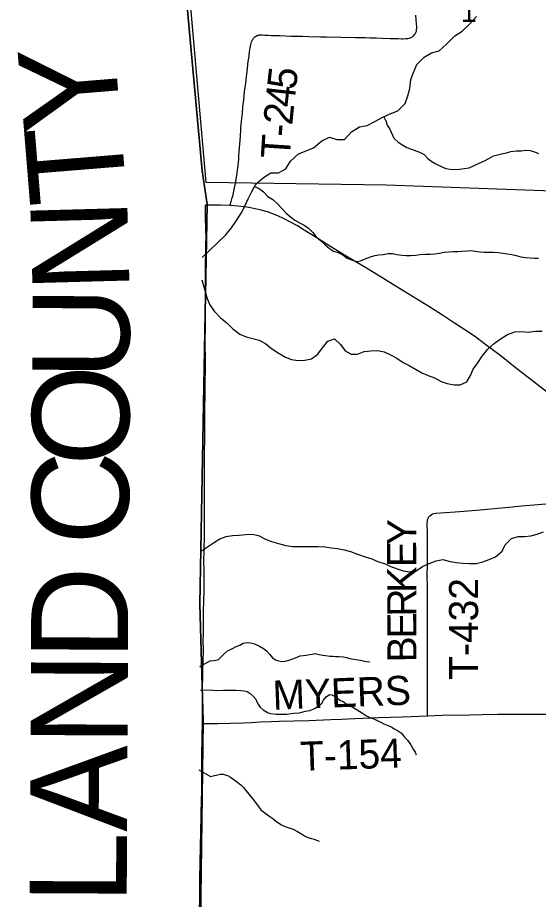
# Model space of a CAD drawing. Extents: x 1985906 to 2360102, y 891258 to 1222054.
# Drawn here: x 2070264 to 2075633, y 1044417 to 1053500 of the extents above; entities that cross this region are included whole.
import ezdxf

# ---------------------------------------------------------------- set-up
doc = ezdxf.new("R2010")
doc.units = 0
for name, color, linetype in [('GM_X_Adjacent_County', 7, 'Continuous'), ('GM_X_Adjacent_County_Text', 7, 'Continuous'), ('GM_X_County', 7, 'Continuous'), ('GM_X_Minor_River', 7, 'Continuous'), ('GM_X_Section', 7, 'Continuous'), ('GM_X_Section_Text', 7, 'Continuous'), ('GM_X_State_Route', 7, 'Continuous'), ('GM_X_Township', 7, 'Continuous'), ('GM_X_Township_Road', 7, 'Continuous'), ('GM_X_Township_Road_Text', 7, 'Continuous')]:
    doc.layers.add(name, color=color, linetype=linetype)

msp = doc.modelspace()

# ---------------------------------------------------------------- linework, layer by layer
at = {"layer": 'GM_X_Adjacent_County'}
msp.add_lwpolyline([(2071926.7, 1054555.3), (2072166.7, 1051922.6), (2072218.3, 1051577.8), (2072142.8, 1047459), (2072178.7, 1046252), (2072112.2, 1041354.4), (2072120.2, 1038512.6), (2072055.1, 1036106.6), (2072018.3, 1033424.1), (2071939.9, 1030867.8), (2071602.1, 1025081.7), (2071562, 1025081.6), (2071696.9, 1021700.4), (2071829.8, 1014456.9), (2071852.3, 1012905.1), (2071861.2, 1011952), (2071887.5, 1008769)], dxfattribs=at)
at = {"layer": 'GM_X_County'}
msp.add_lwpolyline([(2071887.5, 1008769), (2071861.2, 1011952), (2071852.3, 1012905.1), (2071829.8, 1014456.9), (2071696.9, 1021700.4), (2071562, 1025081.6), (2071602.1, 1025081.7), (2071939.9, 1030867.8), (2072018.3, 1033424.1), (2072055.1, 1036106.6), (2072120.2, 1038512.6), (2072112.2, 1041354.4), (2072178.7, 1046252), (2072142.8, 1047459), (2072218.3, 1051577.8), (2072166.7, 1051922.6), (2071926.7, 1054555.3)], dxfattribs=at)
at = {"layer": 'GM_X_Minor_River'}
for points in [[(2072166, 1051027.7), (2072324, 1051178.6), (2072407.5, 1051259.9), (2072468.8, 1051335.4), (2072522.1, 1051411), (2072569.4, 1051484.6), (2072606.6, 1051558.4), (2072641.8, 1051634.3), (2072677, 1051708.1), (2072720.3, 1051783.8), (2072799.6, 1051853.1), (2072874.6, 1051902.3), (2072952.9, 1051901.2), (2073029.8, 1051942.4), (2073077.1, 1052020.1), (2073158.5, 1052095.3), (2073239.3, 1052126.3), (2073316.1, 1052159.5), (2073399.4, 1052230.6), (2073478.3, 1052269.8), (2073554.3, 1052244.6), (2073634.6, 1052245.6), (2073706, 1052322.9), (2073787.1, 1052374.1), (2073867.6, 1052389.1), (2073946.5, 1052430.2), (2074021.4, 1052471.3), (2074106.3, 1052510.4), (2074183.1, 1052541.5), (2074260.5, 1052616.8), (2074285.7, 1052692.7), (2074306.9, 1052770.8), (2074318.2, 1052861), (2074345.4, 1052934.9), (2074380.7, 1053018.8), (2074454.1, 1053094.1), (2074531, 1053137.3), (2074609.6, 1053158.3), (2074684.9, 1053227.6), (2074770.5, 1053312.8), (2074847.5, 1053360), (2074922.8, 1053431.3), (2074994.3, 1053510.6)], [(2074039.3, 1052479.6), (2074059.1, 1052436.7), (2074074.5, 1052392.3), (2074100, 1052349.8), (2074142.9, 1052256.9), (2074186.5, 1052218.1), (2074234.2, 1052185.3), (2074278.1, 1052160.7), (2074324, 1052144), (2074407.9, 1052114.8), (2074455.8, 1052090), (2074493.3, 1052047.3), (2074535.1, 1052016.6), (2074576.9, 1051994), (2074630.7, 1051965.2), (2074678.6, 1051946.5), (2074724.7, 1051939.8), (2074772.9, 1051937.2), (2074819.1, 1051940.6), (2074867.4, 1051945.9), (2074917.7, 1051953.3), (2075022.8, 1052000.1), (2075077.4, 1052025.5), (2075121.9, 1052049), (2075168.5, 1052076.5), (2075210.9, 1052087.9), (2075253.1, 1052095.4), (2075303.5, 1052106.8), (2075347.9, 1052120.3), (2075406.2, 1052127.5), (2075454.4, 1052128.9), (2075500.7, 1052134.3), (2075546.9, 1052131.7), (2075592.9, 1052119), (2075634.8, 1052100.4)], [(2072706.7, 1051760.1), (2072753.8, 1051739.2), (2072797.5, 1051704.5), (2072845, 1051657.7), (2072896.7, 1051624.8), (2072944.3, 1051582.1), (2072991.8, 1051531.2), (2073033.3, 1051484.5), (2073076.9, 1051447.7), (2073120.6, 1051415), (2073176.4, 1051384.1), (2073218.3, 1051363.5), (2073264.1, 1051332.8), (2073307.6, 1051288), (2073343.1, 1051243.4), (2073386.7, 1051204.6), (2073432.3, 1051161.8), (2073480, 1051123.1), (2073521.7, 1051094.4), (2073569.7, 1051079.7), (2073615.6, 1051055), (2073661.3, 1051022.2), (2073705.2, 1051003.6), (2073753.2, 1050988.9), (2073797.5, 1050996.3), (2073845.9, 1051015.7), (2073900.5, 1051037.1), (2073946.9, 1051050.5), (2073989.1, 1051056), (2074033.4, 1051061.4), (2074085.7, 1051068.8), (2074131.9, 1051070.2), (2074173.9, 1051061.6), (2074224, 1051052.9), (2074268.2, 1051050.3), (2074318.4, 1051049.6), (2074366.6, 1051053), (2074412.9, 1051058.4), (2074467.2, 1051061.7), (2074517.4, 1051065), (2074563.6, 1051066.4), (2074611.9, 1051073.8), (2074662.3, 1051083.1), (2074708.5, 1051088.6), (2074754.8, 1051089.9), (2074803, 1051091.3), (2074845.2, 1051094.8), (2074897.5, 1051098.1), (2074939.6, 1051099.5), (2074981.8, 1051094.9), (2075027.8, 1051086.3), (2075074, 1051083.7), (2075118.1, 1051083.1), (2075170.4, 1051084.4), (2075216.5, 1051081.8), (2075264.6, 1051075.1), (2075314.8, 1051068.4), (2075358.8, 1051059.8), (2075404.8, 1051049.1), (2075452.8, 1051034.4), (2075499, 1051029.8), (2075591.2, 1051020.5), (2075633.4, 1051022)], [(2072164.8, 1050797.8), (2072217.4, 1050605.7), (2072246.6, 1050541.1), (2072291.9, 1050476.2), (2072357.2, 1050409.1), (2072420.7, 1050356), (2072484, 1050292.9), (2072555.5, 1050237.7), (2072619.4, 1050212.8), (2072755.5, 1050178.8), (2072819.3, 1050141.8), (2072882.8, 1050090.8), (2072950.5, 1050047.7), (2073024.1, 1050002.5), (2073088.1, 1049979.6), (2073154.1, 1049966.7), (2073224.5, 1049969.8), (2073293, 1049984.9), (2073357.9, 1050032.2), (2073407.1, 1050099.8), (2073462.3, 1050167.4), (2073530.9, 1050190.6), (2073594.3, 1050133.5), (2073639.6, 1050068.6), (2073703.4, 1050033.6), (2073767.6, 1050034.8), (2073838.3, 1050062), (2073906.7, 1050067.1), (2073975, 1050070.2), (2074043.1, 1050057.2), (2074108.9, 1050026.2), (2074174.7, 1049991.2), (2074238.3, 1049948.2), (2074302.2, 1049917.2), (2074365.9, 1049878.2), (2074429.6, 1049841.2), (2074497.5, 1049812.2), (2074561.4, 1049789.2), (2074629.2, 1049752.2), (2074693.1, 1049731.2), (2074763.2, 1049718.2), (2074827.5, 1049717.4), (2074894.2, 1049746.6), (2074931.3, 1049814.4), (2074960.3, 1049880.3), (2075009.5, 1049943.9), (2075052.6, 1050011.6), (2075109.8, 1050081.1), (2075179, 1050146.5), (2075248, 1050193.7), (2075312.9, 1050237.1), (2075389.6, 1050264.1), (2075455.9, 1050267.3), (2075526.1, 1050260.3), (2075602.5, 1050269.3), (2075672.8, 1050270.4)], [(2072149.8, 1047999.6), (2072283.8, 1048090.6), (2072348.7, 1048131.9), (2072413.3, 1048155.1), (2072479.7, 1048164.3), (2072548, 1048169.4), (2072616.4, 1048176.5), (2072682.7, 1048177.6), (2072748.8, 1048164.7), (2072818.5, 1048127.6), (2072882.4, 1048102.7), (2072954.4, 1048081.6), (2073028.5, 1048062.6), (2073096.6, 1048053.6), (2073166.9, 1048050.7), (2073231.2, 1048051.8), (2073299.5, 1048052.9), (2073363.7, 1048052.1), (2073431.9, 1048049.2), (2073498.1, 1048038.2), (2073562.2, 1048031.3), (2073630.3, 1048018.4), (2073696.3, 1047999.4), (2073768.2, 1047972.4), (2073846.2, 1047945.2), (2073914.1, 1047924.2), (2073984, 1047895.2), (2074048, 1047876.3), (2074111.9, 1047847.3), (2074175.7, 1047820.3), (2074239.7, 1047801.4), (2074305.9, 1047792.5), (2074372.3, 1047801.6), (2074439.2, 1047844.9), (2074505.9, 1047876.2), (2074578.6, 1047905.3), (2074649.1, 1047918.4), (2074723.1, 1047897.4), (2074787.2, 1047886.5), (2074855.4, 1047879.5), (2074921.6, 1047876.6), (2074989.9, 1047877.7), (2075060.4, 1047892.9), (2075125, 1047918.1), (2075191.7, 1047945.3), (2075258.8, 1048004.7), (2075289.9, 1048070.5), (2075355.1, 1048135.9), (2075423.7, 1048155.1), (2075489.9, 1048154.2), (2075554.3, 1048161.4), (2075620.8, 1048178.6), (2075685.4, 1048203.8)], [(2072248, 1046872.9), (2072286.8, 1046876.1), (2072306.3, 1046881), (2072336.4, 1046888.2), (2072372.2, 1046924.5), (2072398.2, 1046948.7), (2072428.1, 1046977), (2072458.1, 1046991.2), (2072486, 1047005.4), (2072512, 1047017.5), (2072554, 1047035.8), (2072588, 1047056), (2072628, 1047062.2), (2072666.1, 1047058.4), (2072706.2, 1047048.5), (2072758.4, 1047026.7), (2072798.7, 1047000.8), (2072828.8, 1046976.8), (2072863.1, 1046940.8), (2072891.3, 1046904.8), (2072921.5, 1046884.9), (2072953.6, 1046873), (2072985.7, 1046869.1), (2073021.8, 1046869.3), (2073073.8, 1046885.6), (2073101.8, 1046895.8), (2073127.8, 1046905.9), (2073177.8, 1046924.2), (2073241.9, 1046932.5), (2073271.9, 1046938.7), (2073299.9, 1046942.8), (2073328, 1046949), (2073372.1, 1046939.2), (2073410.2, 1046931.3), (2073438.3, 1046929.4), (2073482.4, 1046923.6), (2073514.5, 1046921.8), (2073542.5, 1046919.9), (2073574.6, 1046918), (2073622.7, 1046916.2), (2073654.8, 1046908.3), (2073684.9, 1046898.4), (2073711, 1046894.5), (2073751.1, 1046888.7), (2073799.2, 1046880.9), (2073827.3, 1046875), (2073861.4, 1046867.1), (2073893.5, 1046865.3)], [(2072141.9, 1046814.2), (2072242.9, 1046871.9), (2072248, 1046872.9)], [(2072277.9, 1046570.7), (2072148, 1046568.7)], [(2072277.9, 1046570.7), (2072312, 1046568.9), (2072388.1, 1046571.2), (2072424.2, 1046571.4), (2072450.2, 1046573.5), (2072488.3, 1046573.7), (2072516.4, 1046571.8), (2072564.5, 1046570), (2072600.6, 1046564.2), (2072630.7, 1046558.3), (2072660.8, 1046538.4), (2072691, 1046510.4), (2072719.2, 1046480.4), (2072731.4, 1046452.4), (2072745.6, 1046426.3), (2072765.8, 1046398.3), (2072794, 1046368.3), (2072846.2, 1046338.4), (2072872.3, 1046330.5), (2072930.5, 1046324.8), (2073034.7, 1046325.3), (2073082.7, 1046331.5), (2073110.8, 1046333.6), (2073166.9, 1046339.9), (2073192.9, 1046346.1), (2073230.9, 1046354.3), (2073274.9, 1046362.5), (2073310.9, 1046376.7), (2073338.9, 1046388.9), (2073364.9, 1046409.1), (2073398.8, 1046439.4), (2073416.7, 1046467.6), (2073446.5, 1046501.8), (2073478.5, 1046526.1), (2073504.5, 1046524.2), (2073548.8, 1046500.3), (2073593, 1046464.3), (2073619.1, 1046454.4), (2073651.3, 1046430.5), (2073677.4, 1046422.6), (2073713.6, 1046400.7), (2073765.9, 1046368.8), (2073820.2, 1046334.9), (2073860.4, 1046307), (2073900.6, 1046287.1), (2073934.7, 1046277.2), (2073970.8, 1046261.3), (2074009, 1046241.4), (2074039.2, 1046225.5), (2074075.3, 1046211.6), (2074121.5, 1046191.7), (2074147.6, 1046173.8), (2074181.8, 1046155.9), (2074220, 1046129.9), (2074252.3, 1046087.9), (2074284.5, 1046056), (2074316.8, 1046007.9), (2074341.1, 1045963.9), (2074361.3, 1045931.8), (2074373.5, 1045905.8)], [(2072133.7, 1045750.1), (2072251.4, 1045682.5)], [(2072251.4, 1045682.5), (2072353.1, 1045705.6), (2072384.7, 1045707.9), (2072426.8, 1045692), (2072459, 1045676.1), (2072493.2, 1045650.2), (2072519.3, 1045632.2), (2072563.6, 1045596.3), (2072593.8, 1045568.3), (2072622, 1045534.3), (2072660.4, 1045484.3), (2072682.6, 1045458.3), (2072747.1, 1045374.3), (2072771.4, 1045340.3), (2072813.6, 1045308.3), (2072853.8, 1045276.4), (2072894.1, 1045248.5), (2072924.2, 1045226.5), (2072976.5, 1045188.6), (2073010.7, 1045172.7), (2073050.9, 1045158.9), (2073103.1, 1045139), (2073149.3, 1045117.2), (2073191.5, 1045091.2), (2073221.6, 1045073.3), (2073255.8, 1045055.4), (2073293.9, 1045045.5), (2073320, 1045037.6), (2073346.1, 1045025.7), (2073372.2, 1045015.8)]]:
    msp.add_lwpolyline(points, dxfattribs=at)
at = {"layer": 'GM_X_Section'}
msp.add_lwpolyline([(2076709.3, 1056959.8), (2076727.4, 1052008.9), (2076733, 1051678.7), (2074064.9, 1051773.8), (2072209.3, 1051803.2), (2071995, 1054235.3), (2071578.8, 1056903.6)], close=True, dxfattribs=at)
at = {"layer": 'GM_X_State_Route'}
msp.add_lwpolyline([(2075725.5, 1049637.2), (2075377.3, 1049910.8), (2075248.1, 1050011.8), (2075091.4, 1050131), (2074986.7, 1050209.9), (2074933.1, 1050247.3), (2074767.7, 1050354), (2074643.3, 1050433.4), (2074491.9, 1050531.5), (2074380.9, 1050601.2), (2074156.5, 1050737.5), (2074030.8, 1050814.7), (2073876.5, 1050907.9), (2073651.9, 1051043.6), (2073483.6, 1051145.7), (2073358, 1051223.5), (2073219.6, 1051311.4), (2073149.4, 1051353.5), (2073078.2, 1051393.6), (2073005.3, 1051430.8), (2072946, 1051458.2), (2072885.4, 1051482.4), (2072839.1, 1051498.1), (2072776.3, 1051516.1), (2072712.6, 1051531.2), (2072648.4, 1051543.5), (2072599.9, 1051550.8), (2072535.1, 1051557.8), (2072453.7, 1051563.4), (2072451.7, 1051563.4), (2072355.7, 1051566.4), (2072199.7, 1051568.1)], dxfattribs=at)
at = {"layer": 'GM_X_Township'}
msp.add_lwpolyline([(2095094.6, 1025388.3), (2092097.4, 1025367.8), (2089225.7, 1025330.9), (2087095.5, 1025303.4), (2086577.8, 1025306.1), (2081728.4, 1025236.6), (2079654.5, 1025204.9), (2076405.9, 1025155.2), (2074264, 1025122.4), (2071602.1, 1025081.7), (2071939.9, 1030867.8), (2072018.3, 1033424.1), (2072055.1, 1036106.6), (2072120.2, 1038512.6), (2072112.2, 1041354.4), (2072178.7, 1046252), (2072142.8, 1047459), (2072218.3, 1051577.8), (2072166.7, 1051922.6), (2071926.7, 1054555.3)], dxfattribs=at)
at = {"layer": 'GM_X_Township_Road'}
for points in [[(2072451.7, 1051563.4), (2072454.2, 1051571.4), (2072464.4, 1051604.2), (2072473.1, 1051633.8), (2072484.8, 1051675.1), (2072497, 1051732.3), (2072508.8, 1051790.2), (2072517.1, 1051834.9), (2072526.4, 1051894.4), (2072531.6, 1051929.8), (2072537.2, 1051976), (2072540.9, 1052012.6), (2072543.7, 1052042.6), (2072546.3, 1052079.1), (2072556.8, 1052233.6), (2072560.4, 1052284.6), (2072564, 1052336.1), (2072566.8, 1052374.1), (2072569, 1052399.9), (2072571.6, 1052427.9), (2072575.5, 1052466.7), (2072577.8, 1052488.5), (2072581.2, 1052520.6), (2072587.5, 1052580.3), (2072594.8, 1052654), (2072604.8, 1052737.3), (2072615.4, 1052823.4), (2072627.4, 1052922.5), (2072633.3, 1052971.3), (2072639, 1053018.7), (2072642.6, 1053047.6), (2072649.7, 1053104.3), (2072655.4, 1053148.8), (2072660.9, 1053187.8), (2072664, 1053204.5), (2072667.8, 1053224.2), (2072671, 1053237.7), (2072675.2, 1053250.1), (2072678.7, 1053257.9), (2072683.6, 1053267.7), (2072687.5, 1053275.9), (2072691.9, 1053282.1), (2072695.4, 1053287.3), (2072702.9, 1053295.4), (2072709.7, 1053301.3), (2072716.5, 1053306.6), (2072725.1, 1053311.5), (2072731.7, 1053314.7), (2072736.7, 1053316.8), (2072744.9, 1053319.2), (2072749.8, 1053320.4), (2072755.5, 1053321.1), (2072761.4, 1053321.4), (2072773, 1053321.5), (2072788.1, 1053321), (2072813.6, 1053319.5), (2072846.2, 1053317.7), (2072878.4, 1053316.7), (2072915.7, 1053315.3), (2072964.3, 1053314.2), (2073024.8, 1053312.2), (2073084.2, 1053310.6), (2073199.3, 1053307.8), (2073265.7, 1053306.3), (2073386.5, 1053303.4), (2073450, 1053301.9), (2073599.4, 1053298.5), (2073746.9, 1053296.2), (2073849.9, 1053293.7), (2073897, 1053292.8), (2073959.3, 1053291.2), (2074025.3, 1053288.9), (2074104.2, 1053286), (2074186.4, 1053283.2), (2074220.2, 1053282.1), (2074237.9, 1053282.1), (2074263.3, 1053283.2), (2074277.1, 1053284.5), (2074287.8, 1053286), (2074301.8, 1053289.1), (2074309.8, 1053291.4), (2074319.3, 1053294.7), (2074326.5, 1053298.4), (2074334.2, 1053303.1), (2074341, 1053308.1), (2074348.3, 1053314.9), (2074356.9, 1053324.9), (2074365.8, 1053337.6), (2074368.3, 1053342.1), (2074370.5, 1053347.1), (2074373.2, 1053353.9), (2074374.6, 1053358.9), (2074376.4, 1053369.5), (2074377.6, 1053379.7), (2074378.3, 1053392.8), (2074378.7, 1053413.3), (2074377.2, 1053434.2), (2074374.1, 1053481.4), (2074369.8, 1053526.8)], [(2072169.4, 1046229.7), (2072170.6, 1046266), (2072169.6, 1046332.1), (2072169.8, 1046386.7), (2072169.1, 1046435.9), (2072169.6, 1046517.7), (2072170.6, 1046567.3), (2072171.6, 1046617.3), (2072173.5, 1046694.8), (2072173.5, 1046762.8), (2072176.3, 1046865.7), (2072179.2, 1046990.4), (2072178.2, 1047078.2), (2072179.2, 1047153.7), (2072180.2, 1047231.2), (2072181.1, 1047371.9), (2072184.9, 1047501.3), (2072185.9, 1047584.4), (2072186.8, 1047651.5), (2072186.7, 1047729.3), (2072185.9, 1047808.3), (2072185, 1047905.5), (2072186.9, 1048008.5), (2072191.6, 1048172.1), (2072191.7, 1048255.9), (2072189.8, 1048352.3), (2072191.2, 1048482.6), (2072190.4, 1048580.7), (2072189.7, 1048662.8), (2072190.4, 1048728.4), (2072191.7, 1048797.1), (2072190.8, 1048850.9), (2072190.4, 1048891), (2072191, 1048940.3), (2072191.8, 1049040.7), (2072192.5, 1049137.4), (2072194.1, 1049200.5), (2072194.4, 1049264.1), (2072195, 1049346), (2072195.7, 1049428.1), (2072197.5, 1049657.5), (2072199.5, 1049971), (2072198.2, 1050150.3), (2072200.4, 1050332.7), (2072201.4, 1050463.1), (2072201.7, 1050609.2), (2072201.5, 1050729.4), (2072201.9, 1050871.6), (2072201.5, 1050974), (2072204.4, 1051084.5), (2072205.3, 1051172.4), (2072206.3, 1051223.4), (2072205.3, 1051321.6), (2072202.5, 1051455.7), (2072199.7, 1051568.1)], [(2074488.8, 1048313.4), (2074491.3, 1048327.1), (2074496.8, 1048342.6), (2074504.8, 1048356.9), (2074515.3, 1048369.6), (2074528, 1048379.9), (2074542.6, 1048387.3), (2074558.4, 1048391.8), (2074574.7, 1048394.2), (2074774.3, 1048408.9), (2074994.8, 1048427.9), (2075360.9, 1048459.7), (2075460.3, 1048470.4), (2075546.2, 1048478.2), (2075750.3, 1048495.5), (2075902.3, 1048510.3), (2076225.3, 1048545.8), (2076400.7, 1048566.7), (2076563.1, 1048584), (2076647.3, 1048593.5), (2076702, 1048600.5), (2076764.3, 1048607.2), (2076794.5, 1048610.4)], [(2074488.2, 1046307.8), (2074488.3, 1046324.9), (2074488.7, 1046438.1), (2074488.4, 1046602.5), (2074488.5, 1046701.1), (2074489.3, 1047003.9), (2074489.3, 1047260.1), (2074489.3, 1047382.5), (2074488.5, 1047637.8), (2074487.8, 1047752.6), (2074489.8, 1047867.7), (2074490.6, 1047966.2), (2074490.6, 1048081.1), (2074489.7, 1048179.5), (2074487.3, 1048294.6), (2074488.3, 1048311), (2074488.8, 1048313.4)], [(2074926.2, 1046319.4), (2075052.3, 1046321.9), (2075216.5, 1046324.7), (2075430, 1046324.2), (2075643.5, 1046323.9), (2075758.4, 1046325.9), (2076070.5, 1046328.3), (2076382.4, 1046334.5), (2076628.8, 1046338.7), (2076776.5, 1046341.3), (2076810.5, 1046341.9)], [(2072169.4, 1046229.7), (2072213.8, 1046228.6), (2072230.2, 1046228.3), (2072328.7, 1046228.5), (2072459.9, 1046231.5), (2072591.1, 1046236.6), (2072673.1, 1046240.6), (2072762, 1046245.5), (2072878.4, 1046249.8), (2072961.7, 1046252.4), (2073116, 1046257.1), (2073266.5, 1046261), (2073494, 1046269.7), (2073604.3, 1046274), (2073739.4, 1046281.3), (2073985.6, 1046289.7), (2074231.7, 1046298), (2074488.2, 1046307.8)], [(2074488.2, 1046307.8), (2074641.9, 1046313.8), (2074926.2, 1046319.4)], [(2072140.1, 1044307.2), (2072141, 1044420.5), (2072142, 1044631.9), (2072148.3, 1044960.2), (2072152.3, 1045107.9), (2072156.7, 1045271.9), (2072157.2, 1045340.4), (2072159.1, 1045399), (2072161, 1045452.8), (2072162.9, 1045519.9), (2072164, 1045566.7), (2072163.9, 1045662.5), (2072162.9, 1045749.4), (2072163.9, 1045913.7), (2072165.8, 1046059.2), (2072166.8, 1046125.3), (2072168.7, 1046205.6), (2072169.4, 1046229.7)]]:
    msp.add_lwpolyline(points, dxfattribs=at)

# ---------------------------------------------------------------- texts
at = {"layer": 'GM_X_Adjacent_County_Text'}
for s, rotation, p in [('Y', 94.66754, (2071331.2, 1052368)), ('T', 94.66754, (2071391.9, 1051623.9)), ('N', 91.56981, (2071419.3, 1050682.6)), ('U', 89.79417, (2071416.5, 1049766.1)), ('O', 89.6922, (2071411.8, 1048881.5)), ('C', 89.69504, (2071407.5, 1048066.3)), ('D', 89.70418, (2071401.3, 1046878.2)), ('N', 89.71018, (2071396.8, 1045995.6)), ('A', 89.7129, (2071392.4, 1045112.9)), ('L', 89.71319, (2071388.7, 1044366.4))]:
    msp.add_text(s, height=1000, rotation=rotation, dxfattribs=at).set_placement(p)
at = {"layer": 'GM_X_Section_Text'}
msp.add_text('1', height=221, rotation=0.00001, dxfattribs=at).set_placement((2074831.6, 1053455.2))
at = {"layer": 'GM_X_Township_Road_Text'}
for s, rotation, p in [('5', 83.57015, (2073132.5, 1052751.5)), ('4', 83.77675, (2073112.5, 1052568.1)), ('2', 84.46234, (2073094.7, 1052385.1)), ('-', 85.18578, (2073084.5, 1052263.3)), ('T', 86.24322, (2073069.9, 1052040.8)), ('Y', 89.27686, (2074372.7, 1048063.2)), ('E', 90.1693, (2074373.4, 1047840.1)), ('K', 90.17235, (2074374.2, 1047576.1)), ('T-432', 90, (2075011.3, 1046678.9)), ('R', 90.17375, (2074374.9, 1047329.7)), ('E', 90.17144, (2074375.6, 1047105.3)), ('B', 90.17369, (2074376.3, 1046858.9)), ('MYERS', 2.17209, (2072898, 1046370)), ('T-154', 1.94647, (2073181.3, 1045740.5))]:
    msp.add_text(s, height=300, rotation=rotation, dxfattribs=at).set_placement(p)

doc.saveas('drawing.dxf')
